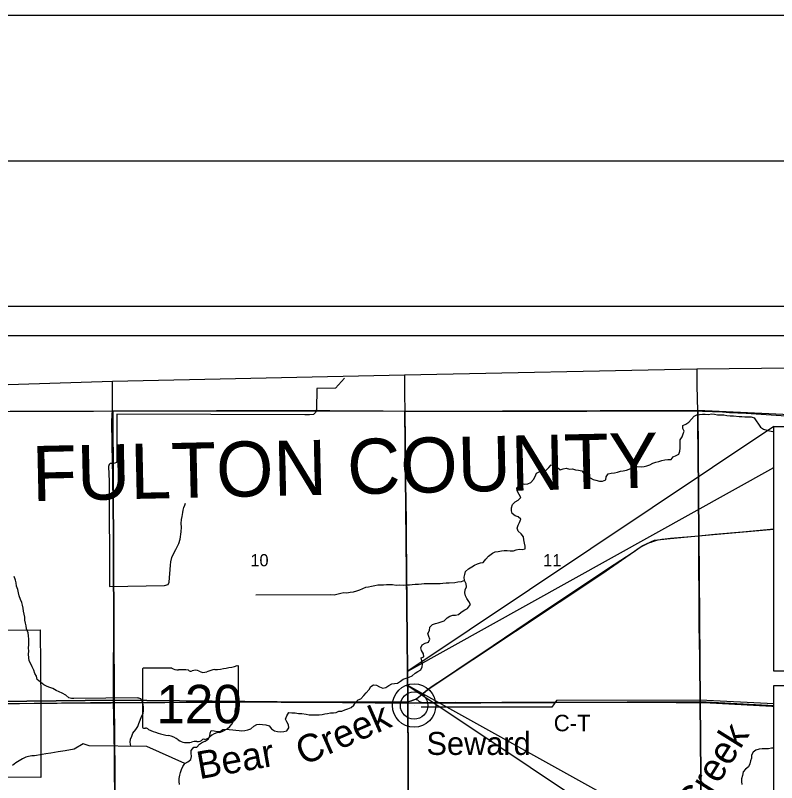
# Model space of a CAD drawing. Extents: x 0 to 34, y 0 to 22.
# Drawn here: x 25.546 to 28.163, y 19.362 to 22 of the extents above; entities that cross this region are included whole.
import ezdxf

# ---------------------------------------------------------------- set-up
doc = ezdxf.new("R2010")
doc.units = 0
for name, color, linetype in [('GM_X_Corporation', 7, 'Continuous'), ('GM_X_County', 7, 'Continuous'), ('GM_X_County_Road', 7, 'Continuous'), ('GM_X_County_Road_Text', 7, 'Continuous'), ('GM_X_County_Text', 7, 'Continuous'), ('GM_X_Minor_River', 7, 'Continuous'), ('GM_X_Minor_River_Text', 7, 'Continuous'), ('GM_X_Rail_Line', 7, 'Continuous'), ('GM_X_Section', 7, 'Continuous'), ('GM_X_Section_Text', 7, 'Continuous'), ('GM_X_State_Route', 7, 'Continuous'), ('GM_X_State_Shield', 7, 'Continuous'), ('GM_X_Township_Road', 7, 'Continuous'), ('GM_X_Unincorporated', 7, 'Continuous'), ('GM_X_Unincorporated_Location', 7, 'Continuous'), ('GM_X_Unincorporated_Text', 7, 'Continuous'), ('SC_Scratch1', 7, 'Continuous'), ('SH_Border', 7, 'Continuous'), ('SH_Cut_Line', 7, 'Continuous'), ('SH_Data', 7, 'Continuous')]:
    doc.layers.add(name, color=color, linetype=linetype)

msp = doc.modelspace()

# ---------------------------------------------------------------- linework, layer by layer
at = {"layer": 'GM_X_Corporation'}
msp.add_lwpolyline([(24.5652, 19.3826), (24.57, 19.633), (24.4536, 19.6328), (24.4515, 19.9027), (24.5624, 19.9018), (24.5612, 20.1354), (24.8773, 20.1361), (25.1302, 20.1369), (25.3811, 20.1379), (25.3819, 19.8854), (25.6319, 19.8878), (25.6346, 19.636), (25.6339, 19.3801), (25.1376, 19.3828), (24.6959, 19.3828)], close=True, dxfattribs=at)
at = {"layer": 'GM_X_County'}
msp.add_lwpolyline([(28.8862, 20.7941), (27.8891, 20.7835), (26.8843, 20.7634), (25.88, 20.7414), (25.1253, 20.7174), (23.8668, 20.6853), (23.5167, 20.6789)], dxfattribs=at)
at = {"layer": 'GM_X_County_Road'}
for points in [[(26.9219, 19.6495), (26.9244, 19.6485), (26.9281, 19.6466), (26.9306, 19.6449), (26.9335, 19.6427), (26.9357, 19.6413), (26.938, 19.6401), (26.9395, 19.6394), (26.9417, 19.6385), (26.9437, 19.6381), (26.9464, 19.6381), (26.9509, 19.6382), (26.9634, 19.6379), (27.0194, 19.6384), (27.0598, 19.6385), (27.1778, 19.6384), (27.2182, 19.6386), (27.3549, 19.6387), (27.414, 19.6388), (27.5724, 19.6386), (27.8178, 19.6384), (27.8893, 19.6382), (27.9008, 19.6379)], [(27.9008, 19.6379), (27.9141, 19.6376), (28.1468, 19.6258), (28.1535, 19.6255)]]:
    msp.add_lwpolyline(points, dxfattribs=at)
at = {"layer": 'GM_X_Minor_River'}
for points in [[(26.6774, 20.7524), (26.6468, 20.7184), (26.5831, 20.7171), (26.5812, 20.6447), (26.578, 20.6345), (26.5711, 20.6277), (26.5571, 20.6267), (26.5415, 20.6265), (25.8948, 20.629), (25.8949, 20.4693), (25.8937, 20.4624), (25.8888, 20.4602), (25.8823, 20.4595), (25.8721, 20.4589), (25.869, 20.4555), (25.867, 20.449), (25.8691, 20.3974), (25.8704, 20.0369), (26.0589, 20.0404), (26.0718, 20.044), (26.0753, 20.0516), (26.0793, 20.1096), (26.081, 20.1217), (26.0846, 20.1358), (26.0923, 20.1531), (26.0978, 20.1641), (26.1086, 20.1845), (26.1133, 20.1992), (26.1162, 20.2246), (26.1179, 20.2409), (26.1166, 20.2535), (26.1179, 20.2667), (26.1195, 20.2777), (26.1215, 20.291), (26.1231, 20.2989), (26.1259, 20.308), (26.129, 20.3159), (26.131, 20.3235)], [(27.5319, 20.405), (27.5417, 20.4022), (27.5538, 20.399), (27.5648, 20.3986), (27.5762, 20.403), (27.5771, 20.4132), (27.584, 20.4238), (27.5939, 20.4263), (27.6053, 20.4277), (27.6159, 20.4295), (27.6258, 20.4336), (27.6357, 20.4343), (27.6463, 20.4364), (27.6562, 20.4401), (27.6658, 20.4442), (27.6756, 20.4472), (27.6859, 20.449), (27.6976, 20.4485), (27.7071, 20.4487), (27.717, 20.4509), (27.7273, 20.4554), (27.7372, 20.4606), (27.7475, 20.4635), (27.7585, 20.4661), (27.7684, 20.4701), (27.7783, 20.4716), (27.7893, 20.473), (27.8003, 20.4729), (27.8076, 20.4827), (27.8171, 20.4864), (27.827, 20.4919), (27.8298, 20.5018), (27.8314, 20.5116), (27.8312, 20.5219), (27.8313, 20.5314), (27.8318, 20.5408), (27.8379, 20.5507), (27.8418, 20.5609), (27.845, 20.5707), (27.8409, 20.5802), (27.8403, 20.5905), (27.8506, 20.5945), (27.8609, 20.602), (27.8701, 20.6122), (27.8789, 20.6223), (27.8888, 20.6264), (27.8983, 20.6275), (27.9078, 20.6293), (27.9177, 20.6295), (27.9283, 20.6283), (27.9385, 20.6297), (27.9488, 20.6296), (27.9601, 20.6265), (27.9809, 20.6263), (27.9919, 20.6242), (28.0037, 20.6234), (28.0143, 20.6236), (28.034, 20.6212), (28.0438, 20.6207), (28.0537, 20.6198), (28.0647, 20.6201), (28.0749, 20.6196), (28.0851, 20.6165), (28.0929, 20.6062), (28.1, 20.5951), (28.1075, 20.584), (28.1176, 20.5775), (28.1286, 20.5736), (28.1384, 20.5712), (28.1494, 20.5699), (28.1535, 20.5709)], [(26.9397, 19.826), (26.9444, 19.8362), (26.9551, 19.8418), (26.9665, 19.8455), (26.9704, 19.8553), (26.9678, 19.8649), (26.9645, 19.8751), (26.9703, 19.8853), (26.9705, 19.8963), (26.9804, 19.9065), (26.9903, 19.909), (26.9998, 19.9116), (27.0204, 19.919), (27.03, 19.9291), (27.0395, 19.9351), (27.0498, 19.938), (27.0592, 19.9383), (27.0691, 19.9405), (27.0791, 19.9484), (27.0909, 19.9566), (27.1008, 19.9614), (27.1108, 19.9746), (27.1049, 19.9853), (27.0978, 19.9949), (27.093, 20.0044), (27.0908, 20.0151), (27.0928, 20.0249), (27.0971, 20.0351), (27.0957, 20.0457), (27.0905, 20.0572), (27.0884, 20.0682), (27.0907, 20.078), (27.0939, 20.0886), (27.1035, 20.0977), (27.1149, 20.1048), (27.1248, 20.1096), (27.1344, 20.1144), (27.1446, 20.1181), (27.1545, 20.1195), (27.1637, 20.1305), (27.1722, 20.1414), (27.1863, 20.1515), (27.1959, 20.1559), (27.2053, 20.1566), (27.2167, 20.1592), (27.2266, 20.1606), (27.2365, 20.1609), (27.2467, 20.1592), (27.2581, 20.1591), (27.2676, 20.1624), (27.2778, 20.1654), (27.2888, 20.1637), (27.2983, 20.1659), (27.2988, 20.1758), (27.2963, 20.1857), (27.2941, 20.1975), (27.2923, 20.2074), (27.2853, 20.218), (27.2751, 20.2269), (27.2707, 20.2372), (27.2742, 20.247), (27.2789, 20.2568), (27.2839, 20.2678), (27.2742, 20.2758), (27.264, 20.279), (27.2542, 20.287), (27.2513, 20.2973), (27.2521, 20.3068), (27.2545, 20.3182), (27.2645, 20.3275), (27.274, 20.3335), (27.284, 20.3429), (27.2781, 20.3532), (27.2714, 20.365), (27.2703, 20.3745), (27.278, 20.3843), (27.288, 20.3911), (27.2978, 20.3887), (27.308, 20.3901), (27.3179, 20.3938), (27.3268, 20.4047), (27.3333, 20.4153), (27.3376, 20.4259), (27.3495, 20.4322), (27.3593, 20.4328), (27.3696, 20.435), (27.3803, 20.4455), (27.3884, 20.4553), (27.399, 20.4537), (27.4095, 20.4456), (27.4193, 20.4379), (27.4292, 20.4409), (27.4394, 20.4431), (27.4504, 20.4399), (27.4614, 20.4406), (27.4712, 20.4382), (27.4814, 20.4366), (27.4928, 20.4342), (27.5014, 20.4238), (27.5115, 20.4158), (27.5319, 20.405)], [(25.7475, 19.6518), (25.7396, 19.6519), (25.7297, 19.6542), (25.72, 19.6627), (25.7079, 19.6696), (25.697, 19.6751), (25.6864, 19.679), (25.6751, 19.6855), (25.6653, 19.6898), (25.6555, 19.6933), (25.6449, 19.6991), (25.6333, 19.7072), (25.6216, 19.7175), (25.6191, 19.7282), (25.6131, 19.7381), (25.6098, 19.7491), (25.6039, 19.7606), (25.5998, 19.7705), (25.5939, 19.7808), (25.5925, 19.7918), (25.5922, 19.804), (25.5931, 19.8146), (25.5913, 19.8256), (25.593, 19.8358), (25.5923, 19.8461), (25.5928, 19.8556), (25.5922, 19.8673), (25.5908, 19.8772), (25.5845, 19.8906), (25.5831, 19.9012), (25.5813, 19.9111), (25.5795, 19.9206), (25.5792, 19.9316), (25.5767, 19.9411), (25.5745, 19.9518), (25.5735, 19.9616), (25.5713, 19.9719), (25.5692, 19.9814), (25.5644, 19.9921), (25.5599, 20.0043), (25.557, 20.0145), (25.5545, 20.0263), (25.5508, 20.0377), (25.5487, 20.0492), (25.5465, 20.0587), (25.5425, 20.0705)], [(27.0905, 20.0572), (27.0791, 20.0531), (27.0677, 20.051), (27.0571, 20.0492), (27.0373, 20.0478), (27.0271, 20.0479), (27.0161, 20.0469), (27.0059, 20.0463), (26.9956, 20.046), (26.9744, 20.0454), (26.9634, 20.0459), (26.9516, 20.0456), (26.9422, 20.045), (26.9323, 20.0439), (26.9209, 20.0437), (26.9103, 20.0423), (26.9008, 20.0416), (26.8891, 20.0417), (26.8792, 20.0395), (26.8655, 20.0416), (26.8549, 20.0405), (26.8424, 20.0418), (26.8223, 20.042), (26.8117, 20.0417), (26.8022, 20.0411), (26.7924, 20.0408), (26.7817, 20.039), (26.7707, 20.0368), (26.7597, 20.0346), (26.7495, 20.0328), (26.7399, 20.0284), (26.7293, 20.0239), (26.719, 20.021), (26.708, 20.0173), (26.6973, 20.0159), (26.6856, 20.0134), (26.675, 20.0146), (26.6651, 20.0124), (26.6556, 20.0099), (26.6426, 20.0073), (26.6286, 20.0075)], [(26.6286, 20.0075), (26.3735, 20.0066)], [(26.1175, 19.4072), (26.1218, 19.4174), (26.1295, 19.4276), (26.139, 19.4339), (26.149, 19.4422), (26.1517, 19.4528), (26.1503, 19.4634), (26.1504, 19.4733), (26.16, 19.4842), (26.1706, 19.4848), (26.1799, 19.495), (26.1894, 19.5014), (26.1989, 19.5054), (26.2089, 19.5118), (26.215, 19.5216), (26.2163, 19.5322), (26.2198, 19.542), (26.2296, 19.5404), (26.2398, 19.5381), (26.2505, 19.5387), (26.26, 19.5451), (26.271, 19.5457), (26.2816, 19.5452), (26.2941, 19.5436), (26.3043, 19.5427), (26.3153, 19.5415), (26.3252, 19.541), (26.335, 19.5421), (26.3449, 19.5435), (26.3556, 19.5479), (26.3659, 19.5562), (26.3766, 19.5618), (26.3861, 19.5639), (26.3963, 19.5623), (26.4076, 19.5615), (26.4186, 19.5572), (26.4268, 19.5472), (26.4374, 19.5403), (26.4476, 19.5379), (26.4586, 19.537), (26.4692, 19.5377), (26.4791, 19.541), (26.486, 19.5508), (26.4857, 19.5611), (26.479, 19.571), (26.475, 19.5805), (26.48, 19.5922), (26.4858, 19.6032), (26.4972, 19.6027), (26.5082, 19.6022), (26.5191, 19.6002), (26.5313, 19.6005), (26.5457, 19.598), (26.5559, 19.596), (26.5676, 19.5956), (26.5797, 19.5951), (26.5911, 19.5953), (26.6006, 19.5964), (26.6101, 19.5986), (26.6196, 19.6004), (26.6291, 19.6018), (26.6397, 19.6028), (26.6492, 19.6035), (26.6587, 19.6076), (26.6682, 19.6078), (26.6785, 19.6123), (26.6891, 19.616), (26.7002, 19.6204), (26.7101, 19.6283), (26.7152, 19.6381), (26.7247, 19.6471), (26.7343, 19.6508), (26.7438, 19.6614), (26.7519, 19.6712), (26.7619, 19.6828), (26.7677, 19.6934), (26.7776, 19.6986), (26.7874, 19.697), (26.798, 19.6916), (26.809, 19.6877), (26.82, 19.6898), (26.8295, 19.6962), (26.8402, 19.7022), (26.8497, 19.7032), (26.8603, 19.7046), (26.8702, 19.7117), (26.8798, 19.7177), (26.8897, 19.721), (26.9, 19.7251), (26.9102, 19.7296), (26.9202, 19.7386), (26.9297, 19.7449), (26.94, 19.7501), (26.9451, 19.7603), (26.9456, 19.7702), (26.9434, 19.7816), (26.9409, 19.7919), (26.9508, 19.7952), (26.9494, 19.8055), (26.9419, 19.8162), (26.9397, 19.826)], [(25.9678, 19.6542), (25.7475, 19.6518)], [(25.9433, 19.4874), (25.9407, 19.5011), (25.9423, 19.5114), (25.9466, 19.522), (25.9505, 19.5325), (25.9602, 19.5453), (25.9671, 19.5555), (25.9706, 19.5657), (25.9749, 19.5771), (25.9796, 19.5896), (25.9862, 19.6005), (25.9874, 19.6107), (25.9864, 19.621), (25.9854, 19.6309), (25.9839, 19.6404), (25.9776, 19.6499), (25.9678, 19.6542), (25.9685, 19.6538)], [(27.4059, 19.645), (27.3901, 19.622), (26.9409, 19.6215)], [(28.1535, 19.633), (27.9006, 19.6458), (27.4059, 19.645)], [(26.1295, 19.4276), (25.9978, 19.4869), (25.8003, 19.4889), (25.7792, 19.4955), (25.7483, 19.4772), (25.7175, 19.4718), (25.6936, 19.4683), (25.6685, 19.4636), (25.6514, 19.4611), (25.6389, 19.4589)], [(28.0917, 19.4742), (28.0821, 19.4671), (28.0764, 19.4569), (28.0759, 19.4467), (28.0735, 19.4368), (28.0711, 19.4266), (28.0661, 19.4164), (28.0561, 19.4089), (28.0481, 19.3991), (28.0453, 19.3866), (28.0425, 19.376), (28.0424, 19.3662), (28.0438, 19.3563)], [(28.1535, 19.4812), (28.1448, 19.4809), (28.1346, 19.4787), (28.1236, 19.4781), (28.1134, 19.4782), (28.1024, 19.4772), (28.0917, 19.4742)], [(25.6389, 19.4589), (25.6123, 19.455), (25.6028, 19.454), (25.5922, 19.4522), (25.5827, 19.4496), (25.5705, 19.444), (25.5594, 19.4373), (25.5476, 19.431), (25.5372, 19.4208)], [(26.1101, 19.3564), (26.1098, 19.3663), (26.1092, 19.3769), (26.112, 19.3875), (26.1144, 19.3973), (26.1175, 19.4072)]]:
    msp.add_lwpolyline(points, dxfattribs=at)
at = {"layer": 'GM_X_Rail_Line'}
msp.add_lwpolyline([(23.5167, 19.628), (23.8789, 19.6294), (24.6464, 19.6305), (25.1346, 19.6322), (26.4299, 19.6404), (26.8953, 19.6404), (26.9248, 19.6506), (26.9689, 19.6865), (27.5616, 20.0799), (27.7012, 20.176), (27.7435, 20.1963), (27.7849, 20.2), (27.8935, 20.211), (28.1535, 20.2337)], dxfattribs=at)
at = {"layer": 'GM_X_Section'}
for points in [[(24.877, 20.6376), (25.8814, 20.6407), (25.8865, 19.646), (24.8865, 19.6346)], [(25.8814, 20.6407), (26.8854, 20.6399), (26.8952, 19.6361), (25.8865, 19.646)], [(26.8854, 20.6399), (27.892, 20.6425), (27.9, 19.6399), (26.8952, 19.6361)], [(24.8865, 19.6346), (25.8865, 19.646), (25.8948, 18.6366), (24.8949, 18.6346)], [(25.8865, 19.646), (26.8952, 19.6361), (26.901, 18.6343), (25.8948, 18.6366)], [(26.8952, 19.6361), (27.9, 19.6399), (27.9094, 18.6339), (26.901, 18.6343)]]:
    msp.add_lwpolyline(points, close=True, dxfattribs=at)
for points in [[(28.1535, 19.6259), (27.9, 19.6399), (27.892, 20.6425), (28.8187, 20.5991), (28.8871, 20.5965), (28.8872, 20.5861)], [(28.9007, 18.8568), (28.9028, 18.5982), (28.9031, 18.5906), (27.9094, 18.6339), (27.9, 19.6399), (28.1535, 19.6259)]]:
    msp.add_lwpolyline(points, dxfattribs=at)
at = {"layer": 'GM_X_State_Route'}
msp.add_line((25.6348, 19.6354), (25.7053, 19.6366), dxfattribs=at)
for points in [[(26.8976, 19.1565), (26.8966, 19.4239), (26.8966, 19.4736), (26.8959, 19.5918), (26.8956, 19.6384), (26.8955, 19.6405), (26.8949, 19.6819), (26.8947, 19.7628), (26.8926, 19.9804), (26.8909, 20.2042), (26.8902, 20.2664), (26.889, 20.3814), (26.8885, 20.4311), (26.8862, 20.6399), (26.8856, 20.6985), (26.8846, 20.7628)], [(26.8955, 19.6405), (26.899, 19.6412), (26.9081, 19.6435), (26.914, 19.6456), (26.9198, 19.6482), (26.9219, 19.6495), (26.9252, 19.6514), (26.9304, 19.6549), (26.9401, 19.6627), (26.9566, 19.677), (26.9662, 19.6848), (26.9788, 19.6938), (27.0178, 19.7194), (27.1056, 19.7783), (27.1882, 19.8338), (27.3482, 19.9414), (27.5165, 20.0534), (27.6044, 20.1122), (27.6692, 20.1552), (27.6905, 20.1692), (27.701, 20.1756), (27.7122, 20.1814), (27.7236, 20.1866), (27.7311, 20.1894), (27.7375, 20.1914), (27.7479, 20.1946), (27.7561, 20.1967), (27.7684, 20.1994), (27.7802, 20.201), (27.7983, 20.2025), (27.895, 20.2113), (27.95, 20.2162), (28.046, 20.2249), (28.142, 20.2335), (28.1535, 20.2345)], [(25.2389, 19.6327), (25.255, 19.6327), (25.2582, 19.6325), (25.2756, 19.6331), (25.338, 19.6331), (25.3433, 19.6331), (25.391, 19.6336), (25.4155, 19.6335), (25.4336, 19.6335), (25.4365, 19.6334), (25.4397, 19.6336), (25.4456, 19.6335), (25.4468, 19.6336), (25.5047, 19.6341), (25.5607, 19.6345), (25.6106, 19.6353), (25.6348, 19.6354)], [(25.7053, 19.6366), (25.7143, 19.6367), (25.8045, 19.6375), (25.8841, 19.6375), (25.8853, 19.6375), (25.8946, 19.6377), (25.9972, 19.6382), (26.134, 19.6395), (26.1651, 19.6394), (26.2211, 19.6392), (26.3019, 19.6395), (26.3424, 19.6396), (26.389, 19.6396), (26.4605, 19.6394), (26.56, 19.6394), (26.6782, 19.6389), (26.7248, 19.6386), (26.7746, 19.6385), (26.8741, 19.6383), (26.8835, 19.6386), (26.8897, 19.6393), (26.8955, 19.6405)]]:
    msp.add_lwpolyline(points, dxfattribs=at)
at = {"layer": 'GM_X_State_Shield'}
for p, q in [((26.0837, 19.7562), (25.9872, 19.7562)), ((26.3135, 19.6564), (26.3135, 19.7611)), ((25.9839, 19.7527), (25.9839, 19.5526)), ((26.3135, 19.6565), (26.3135, 19.6564))]:
    msp.add_line(p, q, dxfattribs=at)
for centre, major_axis, start_param, end_param in [((25.9877, 19.7531), (0.00382, 0), 1.712693, 3.28349), ((26.1067, 19.7794), (0.037, 0), 4.042523, 4.731795), ((26.1961, 20.029), (0.3495, 0), 4.814394, 5.042369), ((26.3099, 19.7615), (0.00367, 0), 6.141152, 7.989035), ((26.119, 19.6438), (0.133, 0), 1.404758, 1.657858), ((26.1492, 19.7542), (0.0107, 0), 3.836095, 5.185415), ((26.1648, 19.731), (0.0222, 0), 0.950623, 2.079405), ((26.1935, 19.7628), (0.0267, 0), 4.081561, 5.145723), ((26.2407, 19.695), (0.0703, 0), 1.699011, 2.107814), ((26.3127, 19.6487), (0.00568, 0), 1.883978, 3.671073), ((26.3096, 19.656), (0.00393, 0), 5.05454, 6.418171), ((26.3267, 19.6126), (0.0248, 0), 2.387724, 3.262537), ((26.2766, 19.6355), (0.0341, 0), 5.934695, 6.695948), ((26.2157, 19.5993), (0.0874, 0), 5.101752, 6.440018), ((25.9878, 19.5522), (0.00385, 0), 3.00124, 4.508301), ((25.9883, 19.5726), (0.0294, 0), 4.665946, 4.897461), ((25.9944, 19.541), (0.0106, 0), 0.519207, 1.627899), ((26.1282, 19.7208), (0.2524, 0), 4.195997, 4.488961), ((26.0529, 19.4627), (0.079, 0), 0.823519, 1.323587), ((26.1919, 19.5332), (0.0282, 0), 4.937069, 5.64225), ((26.2526, 19.4964), (0.0479, 0), 1.647645, 2.488434), ((26.1383, 19.5401), (0.0501, 0), 4.026481, 4.996735), ((26.1673, 19.4709), (0.0412, 0), 1.495662, 1.94098), ((26.171, 19.5251), (0.0267, 0), 4.691044, 5.507374), ((26.1951, 19.5057), (0.00752, 0), 1.147584, 2.315152)]:
    msp.add_ellipse(centre, major_axis=major_axis, ratio=0.8, start_param=start_param, end_param=end_param, dxfattribs=at)
at = {"layer": 'GM_X_Township_Road'}
for points in [[(27.8919, 20.6403), (27.8902, 20.7269), (27.8893, 20.783)], [(25.88, 20.6401), (25.8802, 20.6581), (25.8802, 20.7409)], [(25.1263, 20.6355), (25.2521, 20.6369), (25.3703, 20.6375), (25.4294, 20.638), (25.4636, 20.6383), (25.5289, 20.6389), (25.6596, 20.6391), (25.815, 20.6396), (25.88, 20.6401)], [(25.8841, 19.6375), (25.8842, 19.6585), (25.8835, 19.6957), (25.8834, 19.7268), (25.8833, 19.7392), (25.8841, 19.7858), (25.8844, 19.8354), (25.8844, 19.8882), (25.8845, 19.9441), (25.8848, 19.9938), (25.8846, 20.0186), (25.8844, 20.0869), (25.8836, 20.2297), (25.8819, 20.4129), (25.8805, 20.4688), (25.8792, 20.5216), (25.8785, 20.6085), (25.8789, 20.6207), (25.8795, 20.6326), (25.8799, 20.637), (25.88, 20.6401)], [(25.88, 20.6401), (25.9053, 20.6403), (25.9706, 20.6404), (26.2381, 20.6413), (26.2817, 20.6415), (26.3719, 20.6417), (26.4466, 20.6419), (26.5212, 20.6417), (26.627, 20.6411), (26.8105, 20.6403), (26.8862, 20.6399)], [(26.8862, 20.6399), (26.8949, 20.6398), (26.9726, 20.6394), (27.0317, 20.639), (27.097, 20.6393), (27.1311, 20.6392), (27.2648, 20.6392), (27.4047, 20.6388), (27.4762, 20.6394), (27.5104, 20.6397), (27.6162, 20.6404), (27.7747, 20.6408), (27.8151, 20.6407), (27.8804, 20.6403), (27.8919, 20.6403)], [(27.895, 20.2113), (27.8954, 20.2235), (27.8951, 20.2577), (27.8945, 20.323), (27.8942, 20.41), (27.8928, 20.5312), (27.8925, 20.5529), (27.8924, 20.6026), (27.8919, 20.6368), (27.8919, 20.6403)], [(27.8919, 20.6403), (27.9082, 20.6396), (27.9425, 20.6383), (27.9766, 20.6367), (28.0007, 20.6353), (28.0585, 20.6322), (28.1785, 20.6248), (28.2437, 20.6218), (28.3369, 20.6181), (28.3742, 20.6163), (28.4394, 20.6125), (28.5977, 20.6027), (28.6536, 20.5998), (28.7281, 20.5972), (28.8369, 20.5942), (28.8875, 20.5925)], [(27.8965, 19.957), (27.8962, 19.9811), (27.8956, 20.1303), (27.8953, 20.1769), (27.895, 20.208), (27.895, 20.2113)], [(27.9008, 19.6379), (27.9008, 19.6548), (27.8998, 19.7232), (27.8978, 19.8506), (27.897, 19.9003), (27.8969, 19.9189), (27.8965, 19.957)], [(25.8945, 18.6357), (25.8943, 18.6408), (25.8945, 18.6467), (25.8942, 18.6809), (25.8935, 18.7649), (25.8933, 18.7742), (25.8928, 18.8394), (25.8927, 18.9047), (25.8922, 18.9576), (25.8918, 19.0011), (25.8907, 19.0975), (25.8899, 19.1877), (25.8882, 19.3277), (25.8873, 19.3992), (25.8868, 19.4614), (25.8851, 19.5921), (25.8841, 19.6375)], [(27.9087, 18.6372), (27.9072, 18.7261), (27.9063, 18.7883), (27.9059, 18.8629), (27.9059, 18.8806), (27.9055, 18.9693), (27.9052, 19.0843), (27.905, 19.1153), (27.9043, 19.1961), (27.9033, 19.3142), (27.9021, 19.4106), (27.9013, 19.5367), (27.9007, 19.6113), (27.9008, 19.6379)]]:
    msp.add_lwpolyline(points, dxfattribs=at)
at = {"layer": 'GM_X_Unincorporated'}
for radius in [0.0744, 0.0472]:
    msp.add_circle((26.9168, 19.6276), radius, dxfattribs=at)
at = {"layer": 'GM_X_Unincorporated_Location'}
msp.add_line((26.9168, 19.6276), (26.9168, 19.6276), dxfattribs=at)
at = {"layer": 'SC_Scratch1'}
msp.add_lwpolyline([(23.5167, 20.6789), (23.5167, 15.3175), (30.3167, 15.3175), (30.3167, 20.8109), (30.0181, 20.8047), (28.8862, 20.7941), (27.8891, 20.7835), (26.8843, 20.7634), (25.88, 20.7414), (25.1253, 20.7174), (23.8668, 20.6853)], close=True, dxfattribs=at)
at = {"layer": 'SH_Border'}
msp.add_lwpolyline([(1.5, 21.5), (33.5, 21.5), (33.5, 0.5), (1.5, 0.5)], close=True, dxfattribs=at)
at = {"layer": 'SH_Cut_Line'}
msp.add_lwpolyline([(0, 0), (34, 0), (34, 22), (0, 22)], close=True, dxfattribs=at)
at = {"layer": 'SH_Data'}
for points in [[(23.4167, 21), (30.4167, 21), (30.4167, 14), (23.4167, 14)], [(23.5167, 20.9), (30.3167, 20.9), (30.3167, 15.3175), (23.5167, 15.3175)], [(26.8948, 19.7461), (28.1535, 20.4461), (28.1535, 20.5861)], [(28.1535, 20.5861), (29.7961, 20.5861), (29.7961, 19.7461), (28.1535, 19.7461)], [(26.8948, 19.6968), (28.1535, 18.8568), (28.1535, 18.9968)], [(28.1535, 19.6968), (29.8322, 19.6968), (29.8322, 18.8568), (28.1535, 18.8568)]]:
    msp.add_lwpolyline(points, close=True, dxfattribs=at)

# ---------------------------------------------------------------- texts
at = {"layer": 'GM_X_County_Road_Text'}
msp.add_text('C-T', height=0.05682, rotation=0, dxfattribs=at).set_placement((27.3969, 19.5389))
at = {"layer": 'GM_X_County_Text'}
msp.add_text('FULTON COUNTY', height=0.189394, rotation=1.2494, dxfattribs=at).set_placement((25.6054, 20.3299))
at = {"layer": 'GM_X_Minor_River_Text'}
for s, height, rotation, p in [('Creek', 0.09477, 23.765, (26.5365, 19.4202)), ('Creek', 0.09475, 57.9626, (27.8917, 19.2419)), ('Bear', 0.09476, 10.1383, (26.1791, 19.3739))]:
    msp.add_text(s, height=height, rotation=rotation, dxfattribs=at).set_placement(p)
at = {"layer": 'GM_X_Section_Text'}
for s, p in [('10', (26.3544, 20.106)), ('11', (27.3606, 20.106))]:
    msp.add_text(s, height=0.04186, rotation=0, dxfattribs=at).set_placement(p)
at = {"layer": 'GM_X_State_Shield'}
msp.add_text('120', height=0.13184, dxfattribs=at).set_placement((26.0309, 19.5667))
at = {"layer": 'GM_X_Unincorporated_Text'}
msp.add_text('Seward', height=0.07898, rotation=0, dxfattribs=at).set_placement((26.9594, 19.4576))

doc.saveas('drawing.dxf')
